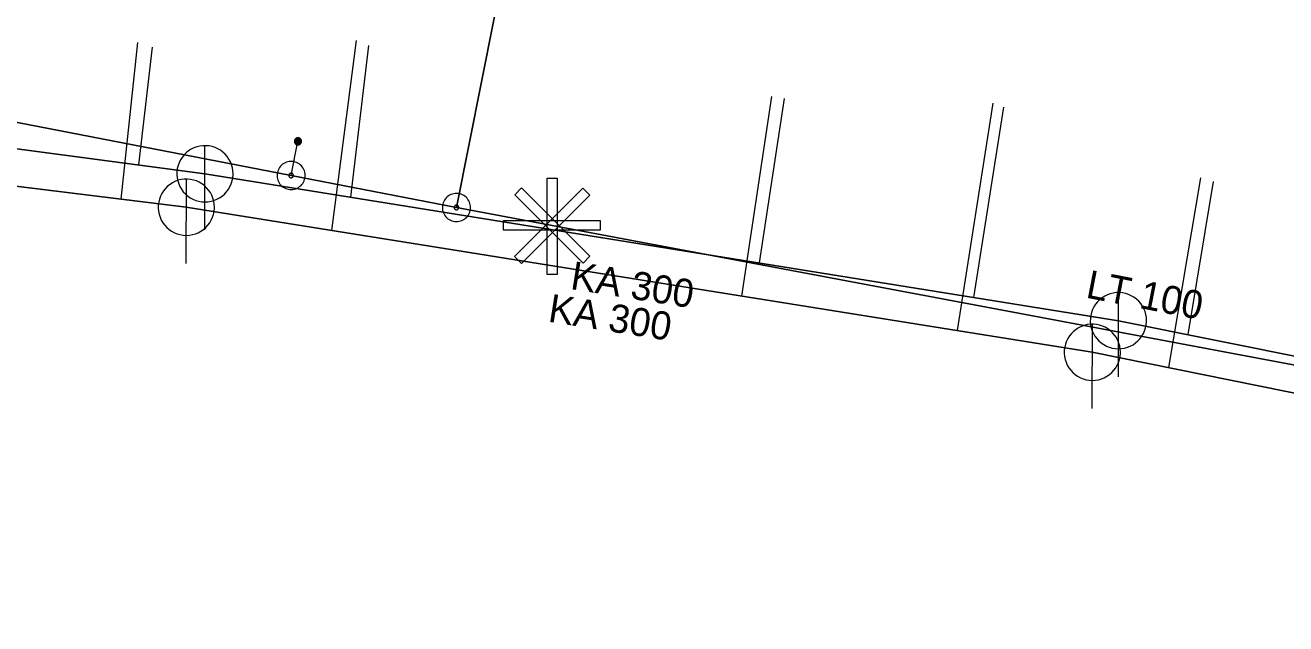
# Model space of a CAD drawing. Extents: x -809028 to -807737, y -990545 to -989489.
# Drawn here: x -808735.91 to -808691.09, y -989800.55 to -989779.26 of the extents above; entities that cross this region are included whole.
import ezdxf

# ---------------------------------------------------------------- set-up
doc = ezdxf.new("R2010")
doc.units = 0
doc.header["$LTSCALE"] = 0.32
for name, color, linetype, lineweight in [('1', 7, 'Continuous', 13), ('11', 7, 'Continuous', 13), ('12', 7, 'Continuous', 13), ('14', 7, 'Continuous', 25), ('17', 7, 'Continuous', 25), ('22', 7, 'Continuous', 13), ('47', 7, 'Continuous', 13), ('9', 7, 'Continuous', 13)]:
    doc.layers.add(name, color=color, linetype=linetype, lineweight=lineweight)

msp = doc.modelspace()

# ---------------------------------------------------------------- linework, layer by layer
at = {"layer": '11'}
for p, q in [((-808731.91, -989779.87), (-808732.508, -989785.442)), ((-808724.144, -989779.801), (-808725.018, -989786.557)), ((-808731.395, -989780.042), (-808731.88, -989784.229)), ((-808723.698, -989779.973), (-808724.334, -989785.374)), ((-808709.369, -989781.794), (-808710.443, -989788.892)), ((-808708.922, -989781.863), (-808709.806, -989787.712)), ((-808701.5, -989782.035), (-808702.773, -989790.12)), ((-808701.122, -989782.172), (-808702.192, -989788.937)), ((-808694.112, -989784.68), (-808695.257, -989791.436)), ((-808693.666, -989784.818), (-808694.569, -989790.262))]:
    msp.add_line(p, q, dxfattribs=at)
at = {"layer": '12'}
for points in [[(-808717.348, -989784.692), (-808716.997, -989784.692), (-808716.997, -989788.127), (-808717.348, -989788.127)], [(-808716.081, -989785.056), (-808715.833, -989785.304), (-808718.262, -989787.733), (-808718.509, -989787.485)], [(-808718.5, -989785.295), (-808718.254, -989785.047), (-808715.825, -989787.476), (-808716.071, -989787.724)], [(-808715.463, -989786.201), (-808715.463, -989786.551), (-808718.899, -989786.551), (-808718.899, -989786.201)]]:
    msp.add_lwpolyline(points, close=True, dxfattribs=at)
at = {"layer": '14'}
for p, q in [((-808761.596, -989780.307), (-808729.515, -989784.541)), ((-808762.191, -989781.763), (-808730.177, -989785.731)), ((-808729.515, -989784.541), (-808697.037, -989789.766)), ((-808730.177, -989785.731), (-808697.964, -989790.891)), ((-808697.037, -989789.766), (-808649.942, -989799.225)), ((-808697.964, -989790.891), (-808650.074, -989800.548))]:
    msp.add_line(p, q, dxfattribs=at)
at = {"layer": '14', "lineweight": 13}
msp.add_line((-808726.451, -989784.602), (-808726.208, -989783.387), dxfattribs=at)
at = {"layer": '17'}
for p, q in [((-808726.451, -989784.602), (-808784.798, -989773.302)), ((-808720.573, -989785.741), (-808726.451, -989784.602)), ((-808720.573, -989785.741), (-808670.355, -989795.186))]:
    msp.add_line(p, q, dxfattribs=at)
msp.add_lwpolyline([(-808715.958, -989759.501), (-808719.237, -989779.008), (-808720.573, -989785.741)], dxfattribs=at)
at = {"layer": '22'}
for p, q in [((-808729.515, -989786.541), (-808729.514, -989783.541)), ((-808730.177, -989787.731), (-808730.176, -989784.731)), ((-808697.037, -989791.766), (-808697.036, -989788.766)), ((-808697.964, -989792.891), (-808697.963, -989789.891))]:
    msp.add_line(p, q, dxfattribs=at)
for points in [[(-808728.515, -989784.541), (-808728.52, -989784.432), (-808728.538, -989784.324), (-808728.568, -989784.218), (-808728.608, -989784.117), (-808728.66, -989784.02), (-808728.722, -989783.93), (-808728.794, -989783.847), (-808728.874, -989783.773), (-808728.962, -989783.707), (-808729.056, -989783.652), (-808729.156, -989783.607), (-808729.261, -989783.574), (-808729.368, -989783.552), (-808729.477, -989783.542), (-808729.587, -989783.544), (-808729.695, -989783.558), (-808729.802, -989783.583), (-808729.905, -989783.62), (-808730.003, -989783.669), (-808730.095, -989783.727), (-808730.181, -989783.796), (-808730.258, -989783.873), (-808730.327, -989783.959), (-808730.386, -989784.051), (-808730.434, -989784.149), (-808730.471, -989784.252), (-808730.497, -989784.359), (-808730.511, -989784.467), (-808730.514, -989784.577), (-808730.504, -989784.686), (-808730.483, -989784.793), (-808730.449, -989784.897), (-808730.405, -989784.997), (-808730.35, -989785.092), (-808730.284, -989785.18), (-808730.21, -989785.26), (-808730.127, -989785.332), (-808730.037, -989785.394), (-808729.941, -989785.446), (-808729.839, -989785.487), (-808729.734, -989785.517), (-808729.626, -989785.535), (-808729.516, -989785.541), (-808729.407, -989785.535), (-808729.299, -989785.517), (-808729.194, -989785.488), (-808729.092, -989785.447), (-808728.995, -989785.395), (-808728.905, -989785.333), (-808728.822, -989785.262), (-808728.747, -989785.182), (-808728.682, -989785.094), (-808728.626, -989785), (-808728.582, -989784.9), (-808728.548, -989784.796), (-808728.526, -989784.688), (-808728.516, -989784.579)], [(-808729.177, -989785.731), (-808729.182, -989785.622), (-808729.2, -989785.514), (-808729.23, -989785.408), (-808729.27, -989785.307), (-808729.322, -989785.21), (-808729.384, -989785.12), (-808729.456, -989785.037), (-808729.536, -989784.963), (-808729.624, -989784.897), (-808729.718, -989784.842), (-808729.818, -989784.797), (-808729.923, -989784.764), (-808730.03, -989784.742), (-808730.139, -989784.732), (-808730.249, -989784.734), (-808730.357, -989784.748), (-808730.464, -989784.773), (-808730.567, -989784.81), (-808730.665, -989784.859), (-808730.757, -989784.917), (-808730.843, -989784.986), (-808730.92, -989785.063), (-808730.989, -989785.149), (-808731.048, -989785.241), (-808731.096, -989785.339), (-808731.133, -989785.442), (-808731.159, -989785.549), (-808731.173, -989785.657), (-808731.176, -989785.767), (-808731.166, -989785.876), (-808731.145, -989785.983), (-808731.111, -989786.087), (-808731.067, -989786.187), (-808731.012, -989786.282), (-808730.946, -989786.37), (-808730.872, -989786.45), (-808730.789, -989786.522), (-808730.699, -989786.584), (-808730.603, -989786.636), (-808730.501, -989786.677), (-808730.396, -989786.707), (-808730.288, -989786.725), (-808730.178, -989786.731), (-808730.069, -989786.725), (-808729.961, -989786.707), (-808729.856, -989786.678), (-808729.754, -989786.637), (-808729.657, -989786.585), (-808729.567, -989786.523), (-808729.484, -989786.452), (-808729.409, -989786.372), (-808729.344, -989786.284), (-808729.288, -989786.19), (-808729.244, -989786.09), (-808729.21, -989785.986), (-808729.188, -989785.878), (-808729.178, -989785.769)], [(-808696.037, -989789.766), (-808696.042, -989789.657), (-808696.06, -989789.549), (-808696.09, -989789.443), (-808696.13, -989789.342), (-808696.182, -989789.245), (-808696.244, -989789.155), (-808696.316, -989789.072), (-808696.396, -989788.998), (-808696.484, -989788.932), (-808696.578, -989788.877), (-808696.678, -989788.832), (-808696.783, -989788.799), (-808696.89, -989788.777), (-808696.999, -989788.767), (-808697.109, -989788.769), (-808697.217, -989788.783), (-808697.324, -989788.808), (-808697.427, -989788.845), (-808697.525, -989788.894), (-808697.617, -989788.952), (-808697.703, -989789.021), (-808697.78, -989789.098), (-808697.849, -989789.184), (-808697.908, -989789.276), (-808697.956, -989789.374), (-808697.993, -989789.477), (-808698.019, -989789.584), (-808698.033, -989789.692), (-808698.036, -989789.802), (-808698.026, -989789.911), (-808698.005, -989790.018), (-808697.971, -989790.122), (-808697.927, -989790.222), (-808697.872, -989790.317), (-808697.806, -989790.405), (-808697.732, -989790.485), (-808697.649, -989790.557), (-808697.559, -989790.619), (-808697.463, -989790.671), (-808697.361, -989790.712), (-808697.256, -989790.742), (-808697.148, -989790.76), (-808697.038, -989790.766), (-808696.929, -989790.76), (-808696.821, -989790.742), (-808696.716, -989790.713), (-808696.614, -989790.672), (-808696.517, -989790.62), (-808696.427, -989790.558), (-808696.344, -989790.487), (-808696.269, -989790.407), (-808696.204, -989790.319), (-808696.148, -989790.225), (-808696.104, -989790.125), (-808696.07, -989790.021), (-808696.048, -989789.913), (-808696.038, -989789.804)], [(-808696.964, -989790.891), (-808696.969, -989790.782), (-808696.987, -989790.674), (-808697.017, -989790.568), (-808697.057, -989790.467), (-808697.109, -989790.37), (-808697.171, -989790.28), (-808697.243, -989790.197), (-808697.323, -989790.123), (-808697.411, -989790.057), (-808697.505, -989790.002), (-808697.605, -989789.957), (-808697.71, -989789.924), (-808697.817, -989789.902), (-808697.926, -989789.892), (-808698.036, -989789.894), (-808698.144, -989789.908), (-808698.251, -989789.933), (-808698.354, -989789.97), (-808698.452, -989790.019), (-808698.544, -989790.077), (-808698.63, -989790.146), (-808698.707, -989790.223), (-808698.776, -989790.309), (-808698.835, -989790.401), (-808698.883, -989790.499), (-808698.92, -989790.602), (-808698.946, -989790.709), (-808698.96, -989790.817), (-808698.963, -989790.927), (-808698.953, -989791.036), (-808698.932, -989791.143), (-808698.898, -989791.247), (-808698.854, -989791.347), (-808698.799, -989791.442), (-808698.733, -989791.53), (-808698.659, -989791.61), (-808698.576, -989791.682), (-808698.486, -989791.744), (-808698.39, -989791.796), (-808698.288, -989791.837), (-808698.183, -989791.867), (-808698.075, -989791.885), (-808697.965, -989791.891), (-808697.856, -989791.885), (-808697.748, -989791.867), (-808697.643, -989791.838), (-808697.541, -989791.797), (-808697.444, -989791.745), (-808697.354, -989791.683), (-808697.271, -989791.612), (-808697.196, -989791.532), (-808697.131, -989791.444), (-808697.075, -989791.35), (-808697.031, -989791.25), (-808696.997, -989791.146), (-808696.975, -989791.038), (-808696.965, -989790.929)]]:
    msp.add_lwpolyline(points, close=True, dxfattribs=at)
at = {"layer": '47'}
for points in [[(-808725.959, -989784.694), (-808725.952, -989784.642), (-808725.951, -989784.59), (-808725.955, -989784.538), (-808725.964, -989784.486), (-808725.979, -989784.436), (-808725.999, -989784.387), (-808726.024, -989784.342), (-808726.054, -989784.299), (-808726.087, -989784.259), (-808726.125, -989784.222), (-808726.167, -989784.19), (-808726.211, -989784.163), (-808726.258, -989784.14), (-808726.308, -989784.123), (-808726.358, -989784.11), (-808726.41, -989784.103), (-808726.462, -989784.102), (-808726.515, -989784.106), (-808726.566, -989784.115), (-808726.616, -989784.13), (-808726.665, -989784.15), (-808726.711, -989784.175), (-808726.754, -989784.204), (-808726.794, -989784.238), (-808726.83, -989784.276), (-808726.862, -989784.318), (-808726.89, -989784.362), (-808726.912, -989784.409), (-808726.929, -989784.459), (-808726.942, -989784.509), (-808726.949, -989784.561), (-808726.95, -989784.613), (-808726.947, -989784.666), (-808726.937, -989784.717), (-808726.922, -989784.767), (-808726.903, -989784.816), (-808726.878, -989784.862), (-808726.848, -989784.905), (-808726.814, -989784.945), (-808726.776, -989784.981), (-808726.734, -989785.013), (-808726.691, -989785.041), (-808726.643, -989785.063), (-808726.593, -989785.08), (-808726.543, -989785.093), (-808726.491, -989785.1), (-808726.439, -989785.101), (-808726.387, -989785.098), (-808726.335, -989785.088), (-808726.285, -989785.073), (-808726.236, -989785.054), (-808726.191, -989785.029), (-808726.148, -989784.999), (-808726.108, -989784.965), (-808726.071, -989784.927), (-808726.039, -989784.885), (-808726.012, -989784.842), (-808725.989, -989784.794), (-808725.972, -989784.744)], [(-808726.37, -989784.617), (-808726.368, -989784.608), (-808726.369, -989784.6), (-808726.369, -989784.591), (-808726.371, -989784.583), (-808726.373, -989784.574), (-808726.377, -989784.567), (-808726.38, -989784.559), (-808726.385, -989784.552), (-808726.391, -989784.546), (-808726.397, -989784.539), (-808726.404, -989784.534), (-808726.412, -989784.529), (-808726.419, -989784.526), (-808726.426, -989784.523), (-808726.435, -989784.521), (-808726.444, -989784.519), (-808726.452, -989784.52), (-808726.461, -989784.52), (-808726.469, -989784.522), (-808726.478, -989784.524), (-808726.485, -989784.528), (-808726.493, -989784.531), (-808726.5, -989784.536), (-808726.507, -989784.542), (-808726.513, -989784.548), (-808726.518, -989784.555), (-808726.523, -989784.563), (-808726.526, -989784.57), (-808726.529, -989784.577), (-808726.531, -989784.586), (-808726.533, -989784.595), (-808726.532, -989784.603), (-808726.532, -989784.612), (-808726.53, -989784.62), (-808726.528, -989784.629), (-808726.525, -989784.636), (-808726.521, -989784.644), (-808726.516, -989784.651), (-808726.51, -989784.658), (-808726.504, -989784.664), (-808726.497, -989784.669), (-808726.489, -989784.674), (-808726.482, -989784.677), (-808726.475, -989784.68), (-808726.466, -989784.682), (-808726.457, -989784.684), (-808726.449, -989784.683), (-808726.44, -989784.683), (-808726.432, -989784.681), (-808726.423, -989784.679), (-808726.416, -989784.676), (-808726.408, -989784.672), (-808726.401, -989784.667), (-808726.395, -989784.661), (-808726.388, -989784.655), (-808726.383, -989784.648), (-808726.378, -989784.64), (-808726.375, -989784.633), (-808726.372, -989784.626)], [(-808720.076, -989785.802), (-808720.073, -989785.75), (-808720.074, -989785.697), (-808720.082, -989785.646), (-808720.094, -989785.595), (-808720.112, -989785.546), (-808720.135, -989785.498), (-808720.163, -989785.455), (-808720.195, -989785.413), (-808720.231, -989785.376), (-808720.271, -989785.342), (-808720.315, -989785.312), (-808720.361, -989785.288), (-808720.409, -989785.268), (-808720.46, -989785.254), (-808720.511, -989785.244), (-808720.563, -989785.241), (-808720.616, -989785.242), (-808720.668, -989785.25), (-808720.718, -989785.262), (-808720.767, -989785.28), (-808720.815, -989785.303), (-808720.859, -989785.331), (-808720.901, -989785.363), (-808720.938, -989785.399), (-808720.971, -989785.439), (-808721.001, -989785.483), (-808721.026, -989785.529), (-808721.045, -989785.577), (-808721.059, -989785.628), (-808721.069, -989785.679), (-808721.072, -989785.731), (-808721.071, -989785.784), (-808721.064, -989785.836), (-808721.051, -989785.886), (-808721.033, -989785.935), (-808721.011, -989785.982), (-808720.983, -989786.027), (-808720.951, -989786.068), (-808720.914, -989786.106), (-808720.874, -989786.139), (-808720.83, -989786.169), (-808720.785, -989786.194), (-808720.736, -989786.213), (-808720.685, -989786.227), (-808720.634, -989786.237), (-808720.582, -989786.24), (-808720.529, -989786.239), (-808720.478, -989786.232), (-808720.427, -989786.219), (-808720.378, -989786.201), (-808720.331, -989786.179), (-808720.287, -989786.151), (-808720.246, -989786.119), (-808720.208, -989786.082), (-808720.174, -989786.042), (-808720.144, -989785.998), (-808720.12, -989785.953), (-808720.1, -989785.904), (-808720.086, -989785.853)], [(-808720.491, -989785.751), (-808720.49, -989785.742), (-808720.491, -989785.733), (-808720.492, -989785.725), (-808720.494, -989785.717), (-808720.497, -989785.709), (-808720.501, -989785.701), (-808720.505, -989785.693), (-808720.51, -989785.687), (-808720.517, -989785.681), (-808720.523, -989785.675), (-808720.531, -989785.67), (-808720.538, -989785.666), (-808720.546, -989785.663), (-808720.553, -989785.66), (-808720.562, -989785.659), (-808720.571, -989785.658), (-808720.58, -989785.659), (-808720.588, -989785.66), (-808720.596, -989785.662), (-808720.604, -989785.665), (-808720.612, -989785.669), (-808720.62, -989785.673), (-808720.626, -989785.678), (-808720.633, -989785.685), (-808720.638, -989785.691), (-808720.643, -989785.699), (-808720.647, -989785.706), (-808720.65, -989785.714), (-808720.653, -989785.721), (-808720.654, -989785.73), (-808720.655, -989785.739), (-808720.654, -989785.748), (-808720.653, -989785.756), (-808720.651, -989785.764), (-808720.648, -989785.772), (-808720.645, -989785.78), (-808720.64, -989785.788), (-808720.635, -989785.794), (-808720.628, -989785.801), (-808720.622, -989785.806), (-808720.614, -989785.811), (-808720.607, -989785.815), (-808720.599, -989785.818), (-808720.592, -989785.821), (-808720.583, -989785.822), (-808720.574, -989785.823), (-808720.565, -989785.822), (-808720.557, -989785.821), (-808720.549, -989785.819), (-808720.541, -989785.816), (-808720.533, -989785.813), (-808720.525, -989785.808), (-808720.519, -989785.803), (-808720.513, -989785.796), (-808720.507, -989785.79), (-808720.502, -989785.782), (-808720.498, -989785.775), (-808720.495, -989785.767), (-808720.492, -989785.76)]]:
    msp.add_lwpolyline(points, close=True, dxfattribs=at)
at = {"layer": '9'}
for points in [[(-808726.334, -989783.387), (-808726.334, -989783.4), (-808726.331, -989783.413), (-808726.329, -989783.426), (-808726.324, -989783.438), (-808726.318, -989783.45), (-808726.311, -989783.461), (-808726.303, -989783.471), (-808726.293, -989783.481), (-808726.282, -989783.489), (-808726.272, -989783.496), (-808726.26, -989783.502), (-808726.248, -989783.507), (-808726.235, -989783.51), (-808726.222, -989783.512), (-808726.209, -989783.514), (-808726.196, -989783.513), (-808726.183, -989783.511), (-808726.17, -989783.508), (-808726.157, -989783.503), (-808726.146, -989783.497), (-808726.135, -989783.49), (-808726.125, -989783.482), (-808726.115, -989783.472), (-808726.107, -989783.462), (-808726.1, -989783.451), (-808726.094, -989783.439), (-808726.089, -989783.427), (-808726.086, -989783.414), (-808726.084, -989783.401), (-808726.081, -989783.388), (-808726.083, -989783.375), (-808726.085, -989783.362), (-808726.088, -989783.349), (-808726.093, -989783.337), (-808726.098, -989783.325), (-808726.106, -989783.314), (-808726.114, -989783.304), (-808726.124, -989783.294), (-808726.134, -989783.286), (-808726.145, -989783.279), (-808726.157, -989783.273), (-808726.169, -989783.268), (-808726.182, -989783.265), (-808726.195, -989783.263), (-808726.208, -989783.262), (-808726.221, -989783.262), (-808726.233, -989783.264), (-808726.247, -989783.267), (-808726.259, -989783.272), (-808726.271, -989783.278), (-808726.282, -989783.285), (-808726.292, -989783.293), (-808726.302, -989783.303), (-808726.309, -989783.313), (-808726.317, -989783.324), (-808726.323, -989783.336), (-808726.328, -989783.348), (-808726.331, -989783.361), (-808726.333, -989783.374)], [(-808726.314, -989783.387), (-808726.315, -989783.398), (-808726.313, -989783.409), (-808726.309, -989783.42), (-808726.306, -989783.43), (-808726.301, -989783.44), (-808726.295, -989783.449), (-808726.288, -989783.458), (-808726.28, -989783.466), (-808726.271, -989783.473), (-808726.262, -989783.479), (-808726.252, -989783.484), (-808726.242, -989783.488), (-808726.231, -989783.491), (-808726.22, -989783.494), (-808726.209, -989783.494), (-808726.198, -989783.494), (-808726.187, -989783.492), (-808726.176, -989783.489), (-808726.166, -989783.485), (-808726.156, -989783.48), (-808726.147, -989783.474), (-808726.138, -989783.467), (-808726.13, -989783.459), (-808726.123, -989783.45), (-808726.117, -989783.441), (-808726.112, -989783.431), (-808726.108, -989783.421), (-808726.105, -989783.41), (-808726.103, -989783.399), (-808726.102, -989783.388), (-808726.102, -989783.377), (-808726.103, -989783.366), (-808726.107, -989783.355), (-808726.111, -989783.345), (-808726.116, -989783.335), (-808726.122, -989783.326), (-808726.129, -989783.317), (-808726.137, -989783.309), (-808726.146, -989783.302), (-808726.155, -989783.296), (-808726.165, -989783.291), (-808726.174, -989783.287), (-808726.186, -989783.284), (-808726.196, -989783.282), (-808726.208, -989783.282), (-808726.219, -989783.281), (-808726.23, -989783.283), (-808726.241, -989783.286), (-808726.25, -989783.29), (-808726.261, -989783.295), (-808726.27, -989783.301), (-808726.279, -989783.308), (-808726.287, -989783.316), (-808726.294, -989783.325), (-808726.299, -989783.334), (-808726.304, -989783.344), (-808726.309, -989783.354), (-808726.312, -989783.365), (-808726.314, -989783.376)], [(-808726.295, -989783.387), (-808726.295, -989783.396), (-808726.294, -989783.405), (-808726.291, -989783.414), (-808726.288, -989783.422), (-808726.284, -989783.43), (-808726.279, -989783.438), (-808726.272, -989783.445), (-808726.267, -989783.451), (-808726.26, -989783.457), (-808726.252, -989783.462), (-808726.244, -989783.466), (-808726.236, -989783.469), (-808726.227, -989783.472), (-808726.218, -989783.473), (-808726.209, -989783.475), (-808726.2, -989783.474), (-808726.191, -989783.473), (-808726.182, -989783.47), (-808726.174, -989783.467), (-808726.166, -989783.463), (-808726.157, -989783.458), (-808726.151, -989783.452), (-808726.145, -989783.446), (-808726.139, -989783.439), (-808726.134, -989783.431), (-808726.13, -989783.423), (-808726.127, -989783.415), (-808726.124, -989783.406), (-808726.123, -989783.397), (-808726.12, -989783.388), (-808726.122, -989783.379), (-808726.123, -989783.37), (-808726.125, -989783.361), (-808726.129, -989783.353), (-808726.133, -989783.345), (-808726.138, -989783.337), (-808726.144, -989783.33), (-808726.15, -989783.324), (-808726.157, -989783.318), (-808726.165, -989783.313), (-808726.173, -989783.309), (-808726.181, -989783.306), (-808726.19, -989783.303), (-808726.199, -989783.302), (-808726.208, -989783.301), (-808726.217, -989783.301), (-808726.226, -989783.302), (-808726.235, -989783.305), (-808726.243, -989783.308), (-808726.25, -989783.312), (-808726.259, -989783.317), (-808726.266, -989783.323), (-808726.272, -989783.329), (-808726.277, -989783.336), (-808726.282, -989783.344), (-808726.287, -989783.352), (-808726.29, -989783.36), (-808726.293, -989783.369), (-808726.294, -989783.378)], [(-808726.275, -989783.387), (-808726.275, -989783.394), (-808726.274, -989783.401), (-808726.272, -989783.408), (-808726.27, -989783.414), (-808726.267, -989783.42), (-808726.263, -989783.426), (-808726.259, -989783.432), (-808726.254, -989783.437), (-808726.248, -989783.441), (-808726.242, -989783.445), (-808726.236, -989783.448), (-808726.23, -989783.451), (-808726.223, -989783.452), (-808726.216, -989783.455), (-808726.209, -989783.455), (-808726.201, -989783.455), (-808726.195, -989783.453), (-808726.188, -989783.452), (-808726.182, -989783.449), (-808726.174, -989783.446), (-808726.17, -989783.442), (-808726.164, -989783.438), (-808726.159, -989783.433), (-808726.155, -989783.427), (-808726.151, -989783.421), (-808726.147, -989783.415), (-808726.145, -989783.409), (-808726.143, -989783.402), (-808726.142, -989783.395), (-808726.141, -989783.388), (-808726.141, -989783.381), (-808726.142, -989783.374), (-808726.144, -989783.367), (-808726.147, -989783.361), (-808726.15, -989783.354), (-808726.154, -989783.349), (-808726.157, -989783.343), (-808726.163, -989783.338), (-808726.169, -989783.334), (-808726.174, -989783.33), (-808726.181, -989783.327), (-808726.187, -989783.324), (-808726.194, -989783.322), (-808726.201, -989783.321), (-808726.208, -989783.321), (-808726.215, -989783.321), (-808726.222, -989783.321), (-808726.228, -989783.323), (-808726.235, -989783.326), (-808726.241, -989783.329), (-808726.247, -989783.333), (-808726.253, -989783.337), (-808726.258, -989783.342), (-808726.262, -989783.348), (-808726.266, -989783.353), (-808726.269, -989783.36), (-808726.272, -989783.366), (-808726.272, -989783.373), (-808726.275, -989783.38)], [(-808726.255, -989783.387), (-808726.255, -989783.392), (-808726.255, -989783.397), (-808726.254, -989783.402), (-808726.252, -989783.406), (-808726.25, -989783.411), (-808726.247, -989783.415), (-808726.244, -989783.418), (-808726.24, -989783.422), (-808726.237, -989783.425), (-808726.233, -989783.428), (-808726.228, -989783.43), (-808726.223, -989783.432), (-808726.219, -989783.433), (-808726.214, -989783.435), (-808726.209, -989783.435), (-808726.204, -989783.435), (-808726.199, -989783.434), (-808726.194, -989783.433), (-808726.19, -989783.431), (-808726.184, -989783.429), (-808726.181, -989783.426), (-808726.177, -989783.423), (-808726.174, -989783.419), (-808726.171, -989783.416), (-808726.168, -989783.412), (-808726.166, -989783.407), (-808726.164, -989783.403), (-808726.163, -989783.398), (-808726.162, -989783.393), (-808726.161, -989783.388), (-808726.161, -989783.383), (-808726.162, -989783.378), (-808726.163, -989783.373), (-808726.165, -989783.369), (-808726.167, -989783.364), (-808726.17, -989783.36), (-808726.173, -989783.356), (-808726.176, -989783.353), (-808726.179, -989783.35), (-808726.184, -989783.347), (-808726.189, -989783.345), (-808726.193, -989783.343), (-808726.198, -989783.342), (-808726.203, -989783.341), (-808726.208, -989783.341), (-808726.213, -989783.341), (-808726.218, -989783.342), (-808726.223, -989783.342), (-808726.227, -989783.344), (-808726.232, -989783.346), (-808726.236, -989783.349), (-808726.239, -989783.352), (-808726.243, -989783.355), (-808726.245, -989783.359), (-808726.249, -989783.363), (-808726.25, -989783.368), (-808726.253, -989783.372), (-808726.254, -989783.377), (-808726.255, -989783.382)], [(-808726.235, -989783.387), (-808726.235, -989783.39), (-808726.236, -989783.393), (-808726.235, -989783.395), (-808726.233, -989783.398), (-808726.233, -989783.401), (-808726.231, -989783.403), (-808726.228, -989783.405), (-808726.227, -989783.407), (-808726.225, -989783.409), (-808726.223, -989783.411), (-808726.22, -989783.413), (-808726.217, -989783.414), (-808726.215, -989783.414), (-808726.212, -989783.415), (-808726.209, -989783.415), (-808726.206, -989783.415), (-808726.203, -989783.415), (-808726.2, -989783.414), (-808726.198, -989783.413), (-808726.195, -989783.412), (-808726.193, -989783.41), (-808726.19, -989783.408), (-808726.188, -989783.406), (-808726.187, -989783.404), (-808726.184, -989783.402), (-808726.184, -989783.399), (-808726.182, -989783.396), (-808726.182, -989783.394), (-808726.181, -989783.391), (-808726.179, -989783.388), (-808726.181, -989783.385), (-808726.181, -989783.382), (-808726.182, -989783.379), (-808726.183, -989783.377), (-808726.184, -989783.374), (-808726.186, -989783.372), (-808726.187, -989783.369), (-808726.189, -989783.367), (-808726.192, -989783.366), (-808726.194, -989783.364), (-808726.196, -989783.363), (-808726.199, -989783.362), (-808726.201, -989783.361), (-808726.205, -989783.361), (-808726.208, -989783.36), (-808726.211, -989783.361), (-808726.214, -989783.36), (-808726.216, -989783.362), (-808726.219, -989783.362), (-808726.222, -989783.363), (-808726.223, -989783.365), (-808726.226, -989783.366), (-808726.228, -989783.368), (-808726.23, -989783.371), (-808726.232, -989783.373), (-808726.233, -989783.376), (-808726.233, -989783.378), (-808726.235, -989783.381), (-808726.235, -989783.384)], [(-808726.216, -989783.387), (-808726.216, -989783.389), (-808726.216, -989783.389), (-808726.215, -989783.389), (-808726.215, -989783.391), (-808726.216, -989783.392), (-808726.214, -989783.392), (-808726.214, -989783.392), (-808726.214, -989783.394), (-808726.214, -989783.394), (-808726.213, -989783.395), (-808726.211, -989783.395), (-808726.211, -989783.395), (-808726.211, -989783.396), (-808726.209, -989783.396), (-808726.209, -989783.396), (-808726.208, -989783.396), (-808726.206, -989783.396), (-808726.206, -989783.395), (-808726.206, -989783.395), (-808726.204, -989783.395), (-808726.204, -989783.394), (-808726.204, -989783.394), (-808726.203, -989783.393), (-808726.203, -989783.393), (-808726.201, -989783.392), (-808726.201, -989783.391), (-808726.2, -989783.39), (-808726.2, -989783.39), (-808726.2, -989783.389), (-808726.2, -989783.388), (-808726.2, -989783.387), (-808726.2, -989783.386), (-808726.2, -989783.386), (-808726.201, -989783.385), (-808726.201, -989783.384), (-808726.201, -989783.383), (-808726.201, -989783.383), (-808726.203, -989783.382), (-808726.203, -989783.382), (-808726.204, -989783.381), (-808726.205, -989783.381), (-808726.206, -989783.38), (-808726.206, -989783.38), (-808726.206, -989783.38), (-808726.208, -989783.38), (-808726.209, -989783.38), (-808726.21, -989783.38), (-808726.21, -989783.38), (-808726.211, -989783.381), (-808726.212, -989783.38), (-808726.213, -989783.382), (-808726.213, -989783.382), (-808726.214, -989783.382), (-808726.214, -989783.382), (-808726.215, -989783.384), (-808726.215, -989783.385), (-808726.215, -989783.386), (-808726.216, -989783.386), (-808726.216, -989783.387)]]:
    msp.add_lwpolyline(points, close=True, dxfattribs=at)

# ---------------------------------------------------------------- texts
at = {"layer": '1'}
for s, rotation, p in [('KA 300', 351, (-808716.553, -989788.637)), ('LT 100', 349, (-808698.229, -989788.94)), ('KA 300', 351, (-808717.346, -989789.797))]:
    msp.add_text(s, height=1, rotation=rotation, dxfattribs=at).set_placement(p)

doc.saveas('drawing.dxf')
